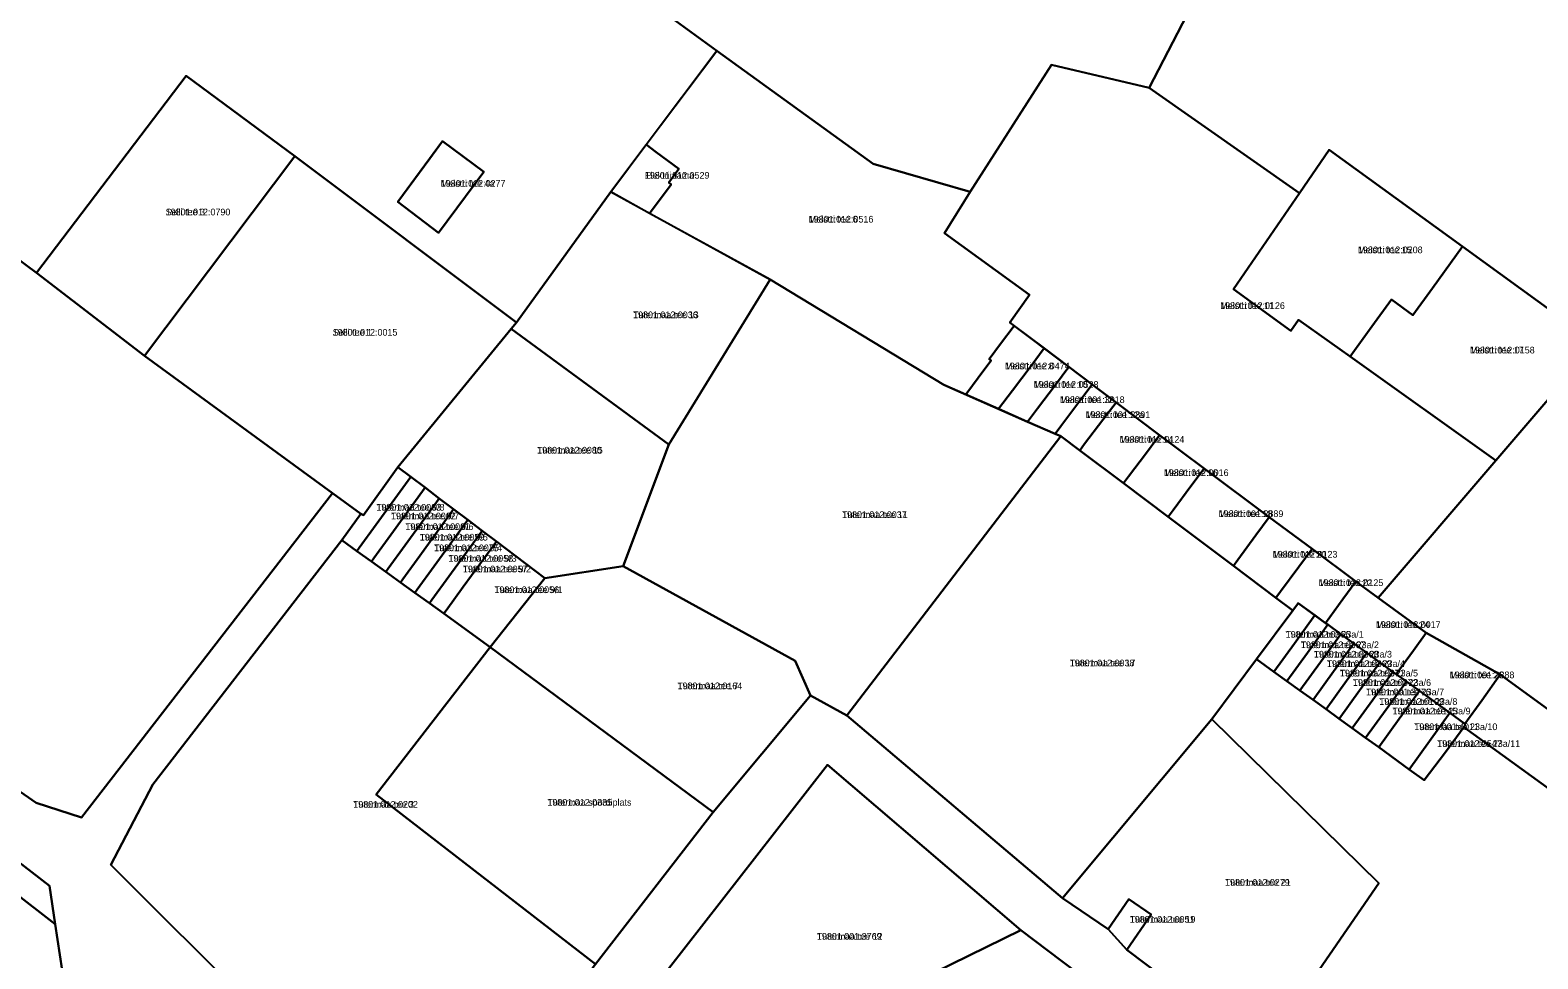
# Model space of a CAD drawing. Extents: x 516875 to 535633, y 6574491 to 6593094.
# Drawn here: x 526817.2 to 527155.2, y 6576664.8 to 6576873.1 of the extents above; entities that cross this region are included whole.
import ezdxf

# ---------------------------------------------------------------- set-up
doc = ezdxf.new("R2010")
doc.units = 0
for name, color, linetype in [('L_AADRESS', 7, 'Continuous'), ('PIIR', 7, 'Continuous'), ('TUNNUS', 7, 'Continuous')]:
    doc.layers.add(name, color=color, linetype=linetype)

msp = doc.modelspace()

# ---------------------------------------------------------------- linework, layer by layer
at = {"layer": 'PIIR'}
for points in [[(527197.55, 6576825.34), (527178.76, 6576814.43), (527168.21, 6576802.84), (527138.28, 6576824.58), (527108.39, 6576846.29), (527101.72, 6576836.57), (527068.06, 6576860.19), (527086.11, 6576895.14), (527067.85, 6576904.74), (527113.88, 6576961.1), (527155.7, 6576944.54), (527186.59, 6576932.58), (527187.47, 6576936.99), (527263.63, 6577039.76), (527266.73, 6577037.59), (527332.17, 6576983.69), (527275.98, 6576910.98)], [(526949.84, 6576908.57), (526993.65, 6576958.04), (527000.79, 6576940.95), (527010.21, 6576935.87), (527067.85, 6576904.74), (527086.11, 6576895.14), (527068.06, 6576860.19), (527046.16, 6576865.35), (527027.92, 6576836.84), (527006.18, 6576843.16), (526971.12, 6576868.51), (526958.81, 6576877.42), (526939.04, 6576893.81)], [(526971.12, 6576868.51), (527006.18, 6576843.16), (527027.92, 6576836.84), (527022.15, 6576827.59), (527041.19, 6576813.72), (527036.79, 6576807.56), (527037.76, 6576806.83), (527034.74, 6576802.76), (527032.18, 6576799.33), (527032.58, 6576799.03), (527031.2, 6576797.16), (527026.91, 6576791.4), (527022, 6576793.56), (526983.07, 6576817.22), (526956.02, 6576832.02), (526960.88, 6576838.51), (526960.32, 6576838.93), (526962.6, 6576841.97), (526957.51, 6576845.78), (526955.3, 6576847.44)], [(527068.06, 6576860.19), (527101.72, 6576836.57), (527086.96, 6576815.05), (527099.79, 6576805.67), (527101.53, 6576808.12), (527113.09, 6576799.88), (527145.75, 6576776.62), (527119.39, 6576745.82), (527114.35, 6576749.46), (527104.56, 6576756.75), (527094.94, 6576763.87), (527080.38, 6576774.79), (527070.37, 6576782.28), (527060.6, 6576789.63), (527055.27, 6576793.65), (527050.04, 6576797.59), (527036.79, 6576807.56), (527041.19, 6576813.72), (527022.15, 6576827.59), (527027.92, 6576836.84), (527046.16, 6576865.35)], [(526876.52, 6576844.86), (526842.8, 6576800.07), (526818.59, 6576818.66), (526852.19, 6576862.85)], [(526763.8, 6576849.32), (526808.5, 6576815.56), (526813.69, 6576822.38), (526818.59, 6576818.66), (526842.8, 6576800.07), (526884.96, 6576769.27), (526828.68, 6576696.53), (526818.56, 6576699.79), (526806.75, 6576707.96), (526716.33, 6576777.92)], [(526918.87, 6576841.37), (526909.62, 6576848.2), (526899.59, 6576834.62), (526908.76, 6576827.67)], [(526909.62, 6576848.2), (526918.87, 6576841.37), (526908.76, 6576827.67), (526899.59, 6576834.62), (526902.14, 6576838.08), (526906.75, 6576844.32)], [(526955.3, 6576847.44), (526957.51, 6576845.78), (526962.6, 6576841.97), (526960.32, 6576838.93), (526960.88, 6576838.51), (526956.02, 6576832.02), (526947.34, 6576836.82)], [(527108.39, 6576846.29), (527138.28, 6576824.58), (527131.54, 6576815.26), (527127.17, 6576809.2), (527122.32, 6576812.71), (527117.95, 6576806.64), (527113.09, 6576799.88), (527101.53, 6576808.12), (527099.79, 6576805.67), (527086.96, 6576815.05), (527101.72, 6576836.57)], [(526876.52, 6576844.86), (526926.22, 6576807.52), (526925.05, 6576806.09), (526899.59, 6576775.12), (526891.89, 6576764.32), (526891.34, 6576764.61), (526884.96, 6576769.27), (526842.8, 6576800.07)], [(526983.07, 6576817.22), (526960.36, 6576780.19), (526925.05, 6576806.09), (526926.22, 6576807.52), (526947.34, 6576836.82)], [(527138.28, 6576824.58), (527168.21, 6576802.84), (527145.75, 6576776.62), (527113.09, 6576799.88), (527117.95, 6576806.64), (527122.32, 6576812.71), (527127.17, 6576809.2), (527131.54, 6576815.26)], [(527197.55, 6576825.34), (527291.43, 6576749.21), (527239.99, 6576673.86), (527233.97, 6576665.05), (527200.84, 6576689.19), (527146.72, 6576728.56), (527130.16, 6576737.96), (527119.39, 6576745.82), (527145.75, 6576776.62), (527168.21, 6576802.84), (527178.76, 6576814.43)], [(526960.36, 6576780.19), (526983.07, 6576817.22), (527022, 6576793.56), (527040.79, 6576785.29), (527046.94, 6576782.58), (527048.25, 6576782.01), (527000.23, 6576719.39), (526992.15, 6576723.87), (526988.69, 6576731.66), (526950.11, 6576752.87)], [(526960.36, 6576780.19), (526950.11, 6576752.87), (526932.57, 6576750.2), (526921.69, 6576758.42), (526918.49, 6576760.84), (526915.29, 6576763.25), (526912.1, 6576765.67), (526908.9, 6576768.08), (526905.71, 6576770.5), (526902.51, 6576772.91), (526899.59, 6576775.12), (526925.05, 6576806.09)], [(527037.76, 6576806.83), (527044.49, 6576801.77), (527041.55, 6576797.84), (527037.41, 6576792.32), (527034.29, 6576788.15), (527026.91, 6576791.4), (527031.2, 6576797.16), (527032.58, 6576799.03), (527032.18, 6576799.33), (527034.74, 6576802.76)], [(527044.49, 6576801.77), (527050.04, 6576797.59), (527047.03, 6576793.59), (527043.02, 6576788.26), (527040.79, 6576785.29), (527034.29, 6576788.15), (527037.41, 6576792.32), (527041.55, 6576797.84)], [(527046.94, 6576782.58), (527040.79, 6576785.29), (527043.02, 6576788.26), (527047.03, 6576793.59), (527050.04, 6576797.59), (527055.27, 6576793.65), (527052.29, 6576789.69), (527048.24, 6576784.31)], [(527048.25, 6576782.01), (527046.94, 6576782.58), (527048.24, 6576784.31), (527052.29, 6576789.69), (527055.27, 6576793.65), (527060.6, 6576789.63), (527057.63, 6576785.68), (527053.57, 6576780.3), (527052.46, 6576778.83)], [(527070.37, 6576782.28), (527067.4, 6576778.32), (527063.38, 6576772.97), (527062.27, 6576771.49), (527052.46, 6576778.83), (527053.57, 6576780.3), (527057.63, 6576785.68), (527060.6, 6576789.63)], [(527048.25, 6576782.01), (527052.46, 6576778.83), (527062.27, 6576771.49), (527072.26, 6576763.93), (527086.9, 6576753), (527096.46, 6576745.79), (527100.21, 6576742.98), (527092.1, 6576732.04), (527082.1, 6576718.54), (527048.59, 6576678.39), (527000.23, 6576719.39)], [(527063.38, 6576772.97), (527067.4, 6576778.32), (527070.37, 6576782.28), (527080.38, 6576774.79), (527077.4, 6576770.8), (527073.39, 6576765.44), (527072.26, 6576763.93), (527062.27, 6576771.49)], [(526902.51, 6576772.91), (526894.76, 6576762.24), (526890.95, 6576757.01), (526890.42, 6576756.28), (526887.09, 6576758.69), (526891.34, 6576764.61), (526891.89, 6576764.32), (526899.59, 6576775.12)], [(526905.71, 6576770.5), (526898.01, 6576759.91), (526894.2, 6576754.67), (526893.67, 6576753.94), (526890.42, 6576756.28), (526890.95, 6576757.01), (526894.76, 6576762.24), (526902.51, 6576772.91)], [(527086.9, 6576753), (527072.26, 6576763.93), (527073.39, 6576765.44), (527077.4, 6576770.8), (527080.38, 6576774.79), (527094.94, 6576763.87), (527091.97, 6576759.85), (527087.87, 6576754.31)], [(526908.9, 6576768.08), (526901.26, 6576757.57), (526897.45, 6576752.33), (526896.92, 6576751.6), (526893.67, 6576753.94), (526894.2, 6576754.67), (526898.01, 6576759.91), (526905.71, 6576770.5)], [(526912.1, 6576765.67), (526904.51, 6576755.23), (526900.7, 6576749.99), (526900.17, 6576749.26), (526896.92, 6576751.6), (526897.45, 6576752.33), (526901.26, 6576757.57), (526908.9, 6576768.08)], [(526915.29, 6576763.25), (526907.77, 6576752.9), (526903.95, 6576747.65), (526903.42, 6576746.92), (526900.17, 6576749.26), (526900.7, 6576749.99), (526904.51, 6576755.23), (526912.1, 6576765.67)], [(526714.09, 6576756.73), (526717.51, 6576761.67), (526821.51, 6576681.2), (526822.81, 6576672.61), (526784.51, 6576702.24), (526770.26, 6576713.27)], [(526918.49, 6576760.84), (526911.02, 6576750.56), (526907.2, 6576745.31), (526906.67, 6576744.58), (526903.42, 6576746.92), (526903.95, 6576747.65), (526907.77, 6576752.9), (526915.29, 6576763.25)], [(527104.56, 6576756.75), (527101.6, 6576752.74), (527097.49, 6576747.18), (527096.46, 6576745.79), (527086.9, 6576753), (527087.87, 6576754.31), (527091.97, 6576759.85), (527094.94, 6576763.87)], [(526887.09, 6576758.69), (526890.42, 6576756.28), (526893.67, 6576753.94), (526896.92, 6576751.6), (526900.17, 6576749.26), (526903.42, 6576746.92), (526906.67, 6576744.58), (526909.92, 6576742.24), (526920.34, 6576734.74), (526894.74, 6576701.66), (526943.92, 6576663.6), (526938.95, 6576657.17), (526908.49, 6576629.24), (526867.34, 6576653.87), (526835.29, 6576685.88), (526844.72, 6576703.93)], [(526921.69, 6576758.42), (526914.27, 6576748.22), (526910.45, 6576742.97), (526909.92, 6576742.24), (526906.67, 6576744.58), (526907.2, 6576745.31), (526911.02, 6576750.56), (526918.49, 6576760.84)], [(526932.57, 6576750.2), (526920.34, 6576734.74), (526909.92, 6576742.24), (526910.45, 6576742.97), (526914.27, 6576748.22), (526921.69, 6576758.42)], [(527114.35, 6576749.46), (527111.44, 6576745.45), (527107.57, 6576740.11), (527101.4, 6576744.59), (527101.26, 6576744.4), (527100.21, 6576742.98), (527096.46, 6576745.79), (527097.49, 6576747.18), (527101.6, 6576752.74), (527104.56, 6576756.75)], [(526932.57, 6576750.2), (526950.11, 6576752.87), (526988.69, 6576731.66), (526992.15, 6576723.87), (526970.3, 6576697.7), (526920.34, 6576734.74)], [(527130.16, 6576737.96), (527127.27, 6576733.97), (527123.42, 6576728.63), (527122.68, 6576729.17), (527119.74, 6576731.3), (527116.81, 6576733.42), (527113.9, 6576735.53), (527110.97, 6576737.65), (527108.05, 6576739.77), (527107.57, 6576740.11), (527111.44, 6576745.45), (527114.35, 6576749.46), (527119.39, 6576745.82)], [(527101.4, 6576744.59), (527105.15, 6576741.87), (527100.61, 6576735.58), (527096.01, 6576729.21), (527092.1, 6576732.04), (527100.21, 6576742.98), (527101.26, 6576744.4)], [(527105.15, 6576741.87), (527107.57, 6576740.11), (527108.05, 6576739.77), (527103.5, 6576733.48), (527098.91, 6576727.12), (527096.01, 6576729.21), (527100.61, 6576735.58)], [(527108.05, 6576739.77), (527110.97, 6576737.65), (527106.43, 6576731.37), (527101.84, 6576725), (527098.91, 6576727.12), (527103.5, 6576733.48)], [(527125.68, 6576727.02), (527123.42, 6576728.63), (527127.27, 6576733.97), (527130.16, 6576737.96), (527146.72, 6576728.56), (527142.57, 6576722.76), (527138.82, 6576717.54), (527135.45, 6576719.97), (527128.61, 6576724.91)], [(526920.34, 6576734.74), (526970.3, 6576697.7), (526943.92, 6576663.6), (526894.74, 6576701.66)], [(527110.97, 6576737.65), (527113.9, 6576735.53), (527109.36, 6576729.25), (527104.76, 6576722.89), (527101.84, 6576725), (527106.43, 6576731.37)], [(527113.9, 6576735.53), (527116.81, 6576733.42), (527112.28, 6576727.14), (527107.68, 6576720.78), (527104.76, 6576722.89), (527109.36, 6576729.25)], [(527092.1, 6576732.04), (527096.01, 6576729.21), (527098.91, 6576727.12), (527101.84, 6576725), (527104.76, 6576722.89), (527107.68, 6576720.78), (527110.61, 6576718.67), (527113.55, 6576716.54), (527116.55, 6576714.38), (527119.48, 6576712.26), (527126.3, 6576707.31), (527129.69, 6576704.86), (527134.44, 6576711.18), (527138.57, 6576716.77), (527192.75, 6576677.52), (527210.16, 6576664.9), (527218.42, 6576676.4), (527233.97, 6576665.05), (527147.6, 6576615.77), (527093.4, 6576643.88), (527119.52, 6576681.8), (527082.1, 6576718.54)], [(527116.81, 6576733.42), (527119.74, 6576731.3), (527115.2, 6576725.03), (527110.61, 6576718.67), (527107.68, 6576720.78), (527112.28, 6576727.14)], [(527115.2, 6576725.03), (527119.74, 6576731.3), (527122.68, 6576729.17), (527118.15, 6576722.9), (527113.55, 6576716.54), (527110.61, 6576718.67)], [(527123.42, 6576728.63), (527125.68, 6576727.02), (527121.14, 6576720.74), (527116.55, 6576714.38), (527113.55, 6576716.54), (527118.15, 6576722.9), (527122.68, 6576729.17)], [(527200.84, 6576689.19), (527192.75, 6576677.52), (527138.57, 6576716.77), (527138.86, 6576717.17), (527138.82, 6576717.54), (527142.57, 6576722.76), (527146.72, 6576728.56)], [(527125.68, 6576727.02), (527128.61, 6576724.91), (527124.07, 6576718.62), (527119.48, 6576712.26), (527116.55, 6576714.38), (527121.14, 6576720.74)], [(527119.48, 6576712.26), (527124.07, 6576718.62), (527128.61, 6576724.91), (527135.45, 6576719.97), (527130.9, 6576713.67), (527126.3, 6576707.31)], [(527048.59, 6576678.39), (527082.1, 6576718.54), (527119.52, 6576681.8), (527093.4, 6576643.88), (527063.03, 6576666.82), (527068.51, 6576674.78), (527063.49, 6576678.23), (527058.85, 6576671.49)], [(527126.3, 6576707.31), (527130.9, 6576713.67), (527135.45, 6576719.97), (527138.82, 6576717.54), (527138.86, 6576717.17), (527138.57, 6576716.77), (527134.44, 6576711.18), (527129.69, 6576704.86)], [(526995.96, 6576708.31), (527039.29, 6576671.26), (527008.17, 6576655.98), (526985.31, 6576620.01), (526947.81, 6576649.02), (526952.39, 6576652.41)], [(526749.98, 6576653.31), (526784.51, 6576702.24), (526822.81, 6576672.61), (526827.5, 6576641.62), (526807.22, 6576612.91)], [(527068.51, 6576674.78), (527063.03, 6576666.82), (527058.85, 6576671.49), (527063.49, 6576678.23)], [(527076.65, 6576643), (527030.33, 6576585), (526985.31, 6576620.01), (527008.17, 6576655.98), (527039.29, 6576671.26)]]:
    msp.add_lwpolyline(points, close=True, dxfattribs=at)
for points in [[(526795.19, 6576892.83), (526817.69, 6576876.59), (526831.05, 6576885.14), (526855.5, 6576917.81), (526851.03, 6576921.15), (526853.89, 6576924.97), (526854.03, 6576925.16), (526848.37, 6576929.39), (526855.5, 6576938.92), (526855.74, 6576938.74), (526856.92, 6576937.85), (526863.04, 6576946.03), (526879.24, 6576933.85), (526892.35, 6576951.28), (526949.84, 6576908.57), (526939.04, 6576893.81), (526958.81, 6576877.42), (526971.12, 6576868.51), (526947.34, 6576836.82), (526926.22, 6576807.52), (526876.52, 6576844.86), (526852.19, 6576862.85), (526818.59, 6576818.66), (526813.69, 6576822.38)], [(526806.75, 6576707.96), (526818.56, 6576699.79), (526828.68, 6576696.53), (526884.96, 6576769.27), (526891.34, 6576764.61), (526887.09, 6576758.69), (526844.72, 6576703.93), (526835.29, 6576685.88), (526867.34, 6576653.87), (526908.49, 6576629.24), (526938.95, 6576657.17), (526943.92, 6576663.6), (526970.3, 6576697.7), (526992.15, 6576723.87), (527000.23, 6576719.39), (527048.59, 6576678.39), (527058.85, 6576671.49), (527063.03, 6576666.82), (527093.4, 6576643.88), (527147.6, 6576615.77), (527233.97, 6576665.05), (527239.99, 6576673.86), (527280.52, 6576644.51), (527414.06, 6576546.66)], [(526827.5, 6576641.62), (526822.81, 6576672.61), (526821.51, 6576681.2), (526717.51, 6576761.67)], [(527076.65, 6576643), (527039.29, 6576671.26), (526995.96, 6576708.31), (526952.39, 6576652.41)]]:
    msp.add_lwpolyline(points, dxfattribs=at)

# ---------------------------------------------------------------- texts
at = {"layer": 'L_AADRESS'}
for s, p in [('Meistri tee 4a', (526909.23, 6576837.99)), ('Elektrijaama', (526954.97, 6576839.8)), ('Selli tee 3', (526847.56, 6576831.57)), ('Meistri tee 6', (526991.71, 6576829.96)), ('Meistri tee 15', (527114.83, 6576823.08)), ('Tutermaa tee 13', (526952.33, 6576808.51)), ('Meistri tee 11', (527083.95, 6576810.58)), ('Selli tee 1', (526885.01, 6576804.59)), ('Meistri tee 17', (527139.95, 6576800.6)), ('Meistri tee 8', (527035.7, 6576797.04)), ('Meistri tee 10', (527042.16, 6576792.89)), ('Meistri tee 12', (527048.03, 6576789.47)), ('Meistri tee 12a', (527053.77, 6576786.11)), ('Meistri tee 14', (527061.41, 6576780.57)), ('Tutermaa tee 15', (526930.83, 6576778.15)), ('Meistri tee 16', (527071.33, 6576773.1)), ('Tutermaa tee 9/8', (526894.8, 6576765.35)), ('Tutermaa tee 11', (526999.18, 6576763.7)), ('Meistri tee 18', (527083.61, 6576763.9)), ('Tutermaa tee 9/7', (526898.07, 6576763.39)), ('Tutermaa tee 9/6', (526901.29, 6576761.01)), ('Tutermaa tee 9/5', (526904.51, 6576758.64)), ('Tutermaa tee 9/4', (526907.73, 6576756.25)), ('Tutermaa tee 9/3', (526910.96, 6576753.88)), ('Meistri tee 20', (527095.73, 6576754.81)), ('Tutermaa tee 9/2', (526914.18, 6576751.5)), ('Tutermaa tee 9/1', (526921.25, 6576746.85)), ('Meistri tee 22', (527106.01, 6576748.43)), ('Tutermaa tee 23a/1', (527098.62, 6576736.84)), ('Meistri tee 24', (527118.86, 6576739.04)), ('Tutermaa tee 23a/2', (527102.03, 6576734.5)), ('Tutermaa tee 17', (527050.22, 6576730.43)), ('Tutermaa tee 23a/3', (527104.94, 6576732.39)), ('Tutermaa tee 23a/4', (527107.87, 6576730.28)), ('Tutermaa tee 23a/5', (527110.79, 6576728.15)), ('Meistri tee 26', (527135.4, 6576727.75)), ('Tutermaa tee 7', (526962.31, 6576725.29)), ('Tutermaa tee 23a/6', (527113.71, 6576726.04)), ('Tutermaa tee 23a/7', (527116.64, 6576723.92)), ('Tutermaa tee 23a/8', (527119.61, 6576721.78)), ('Tutermaa tee 23a/9', (527122.58, 6576719.64)), ('Tutermaa tee 23a/10', (527127.46, 6576716.12)), ('Tutermaa tee 23a/11', (527132.58, 6576712.35)), ('Tutermaa tee 3', (526889.61, 6576698.71)), ('Tutermaa spordiplats', (526933.14, 6576699.17)), ('Tutermaa tee 21', (527085.03, 6576681.21)), ('Tutermaa tee 19', (527063.68, 6576672.93)), ('Tutermaa tee 12', (526993.55, 6576669.1))]:
    msp.add_text(s, height=1.5, dxfattribs=at).set_placement(p)
at = {"layer": 'TUNNUS'}
for s, p in [('19801:012:0277', (526909.23, 6576837.99)), ('19801:012:0529', (526954.97, 6576839.8)), ('19801:012:0790', (526847.56, 6576831.57)), ('19801:012:0516', (526991.71, 6576829.96)), ('19801:012:0208', (527114.83, 6576823.08)), ('19801:012:0036', (526952.33, 6576808.51)), ('19801:012:0126', (527083.95, 6576810.58)), ('19801:012:0015', (526885.01, 6576804.59)), ('19801:012:0158', (527139.95, 6576800.6)), ('19801:012:0474', (527035.7, 6576797.04)), ('19801:012:0528', (527042.16, 6576792.89)), ('19801:001:3018', (527048.03, 6576789.47)), ('19801:001:2891', (527053.77, 6576786.11)), ('19801:012:0124', (527061.41, 6576780.57)), ('19801:012:0080', (526930.83, 6576778.15)), ('19801:012:0016', (527071.33, 6576773.1)), ('19801:012:0063', (526894.8, 6576765.35)), ('19801:012:0037', (526999.18, 6576763.7)), ('19801:001:2889', (527083.61, 6576763.9)), ('19801:012:0062', (526898.07, 6576763.39)), ('19801:012:0061', (526901.29, 6576761.01)), ('19801:012:0059', (526904.51, 6576758.64)), ('19801:012:0075', (526907.73, 6576756.25)), ('19801:012:0058', (526910.96, 6576753.88)), ('19801:012:0123', (527095.73, 6576754.81)), ('19801:012:0057', (526914.18, 6576751.5)), ('19801:012:0056', (526921.25, 6576746.85)), ('19801:012:0125', (527106.01, 6576748.43)), ('19801:012:0366', (527098.62, 6576736.84)), ('19801:012:0017', (527118.86, 6576739.04)), ('19801:012:0367', (527102.03, 6576734.5)), ('19801:012:0038', (527050.22, 6576730.43)), ('19801:012:0368', (527104.94, 6576732.39)), ('19801:012:0369', (527107.87, 6576730.28)), ('19801:012:0371', (527110.79, 6576728.15)), ('19801:001:2888', (527135.4, 6576727.75)), ('19801:012:0164', (526962.31, 6576725.29)), ('19801:012:0372', (527113.71, 6576726.04)), ('19801:001:3776', (527116.64, 6576723.92)), ('19801:012:0109', (527119.61, 6576721.78)), ('19801:012:0145', (527122.58, 6576719.64)), ('19801:001:4011', (527127.46, 6576716.12)), ('19801:012:0547', (527132.58, 6576712.35)), ('19801:012:0202', (526889.61, 6576698.71)), ('19801:012:0335', (526933.14, 6576699.17)), ('19801:012:0279', (527085.03, 6576681.21)), ('19801:012:0051', (527063.68, 6576672.93)), ('19801:001:3769', (526993.55, 6576669.1))]:
    msp.add_text(s, height=1.5, dxfattribs=at).set_placement(p)

doc.saveas('drawing.dxf')
